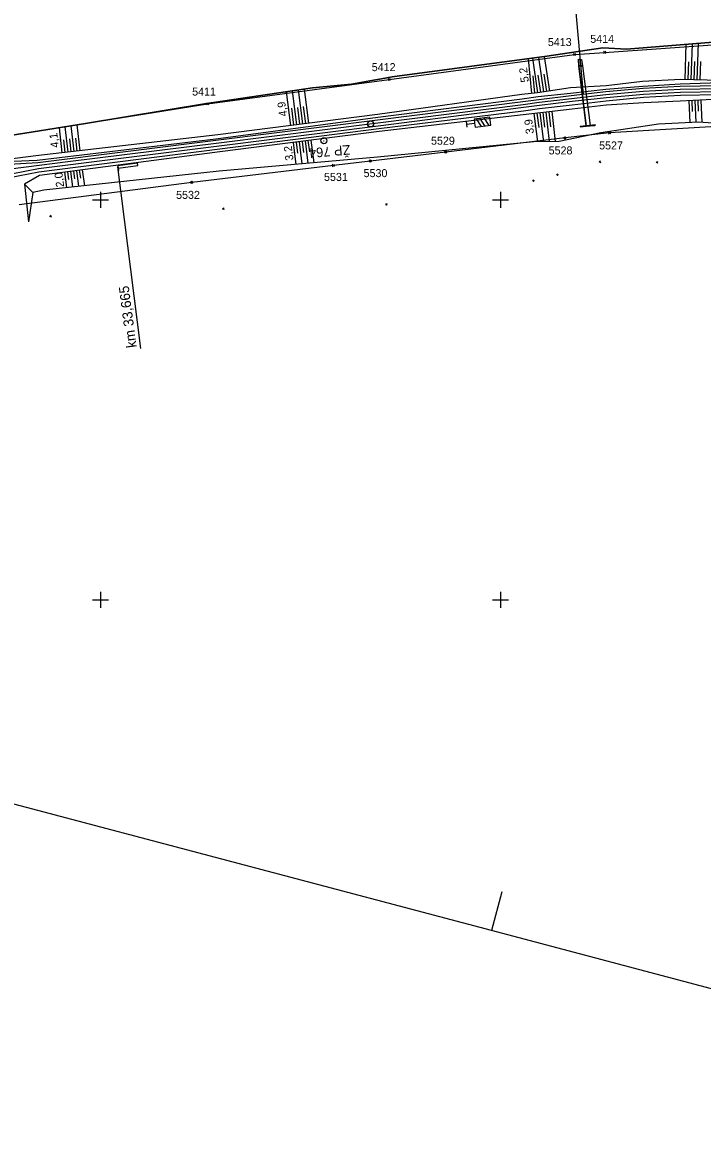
# Model space of a CAD drawing. Extents: x -805011 to -803920, y -1150790 to -1150234.
# Drawn here: x -804519.5 to -804349.5, y -1150736.4 to -1150455.7 of the extents above; entities that cross this region are included whole.
import ezdxf

# ---------------------------------------------------------------- set-up
doc = ezdxf.new("R2010")
doc.units = 0
for name, color, linetype in [('0381KM032-037P - Vrstva 1', 7, 'Continuous'), ('0381KM032-037P - Vrstva 17', 7, 'Continuous'), ('0381KM032-037P - Vrstva 19', 7, 'Continuous'), ('0381KM032-037P - Vrstva 4', 7, 'Continuous'), ('0381KM032-037P - Vrstva 48', 7, 'Continuous'), ('0381KM032-037P - Vrstva 49', 7, 'Continuous'), ('0381KM032-037P - Vrstva 7', 7, 'Continuous'), ('0381KM032-037P - Vrstva 9', 7, 'Continuous'), ('formát', 7, 'Continuous'), ('krizky_1000 - Vrstva 1', 7, 'Continuous'), ('szdc - hran DP', 7, 'Continuous'), ('szdc - szdc_cislo', 7, 'Continuous'), ('szdc - szdc_krizek', 7, 'Continuous'), ('vyt_sit - stávající', 7, 'Continuous')]:
    doc.layers.add(name, color=color, linetype=linetype)

msp = doc.modelspace()

# ---------------------------------------------------------------- linework, layer by layer
at = {"layer": '0381KM032-037P - Vrstva 1'}
for points in [[(-804345.19, -1150472.22), (-804355.1, -1150472.39), (-804364.37, -1150472.93), (-804373.68, -1150473.77), (-804382.25, -1150474.73), (-804390.38, -1150475.71), (-804394.38, -1150476.22)], [(-804394.38, -1150476.22), (-804430.66, -1150480.81), (-804470.38, -1150485.81), (-804485.9, -1150487.74)], [(-804485.9, -1150487.74), (-804508.11, -1150490.55), (-804529.67, -1150493.3), (-804537.63, -1150494.31), (-804546.61, -1150495.46), (-804554.2, -1150496.42), (-804564.05, -1150497.67), (-804586.01, -1150500.48), (-804607.92, -1150503.26), (-804630.35, -1150506.11), (-804652.65, -1150508.9), (-804675.7, -1150511.78), (-804698.85, -1150514.71), (-804701.61, -1150515.06), (-804722.18, -1150517.67), (-804729.05, -1150518.54), (-804735.1, -1150519.31), (-804744.56, -1150520.5), (-804767.65, -1150523.46), (-804791, -1150526.42)]]:
    msp.add_lwpolyline(points, dxfattribs=at)
at = {"layer": '0381KM032-037P - Vrstva 17'}
for points in [[(-804328.85, -1150461.67), (-804338.71, -1150460.38), (-804346.87, -1150460.56), (-804368.54, -1150462.33)], [(-804368.54, -1150462.33), (-804374.42, -1150462.03), (-804388.45, -1150464.13), (-804427.08, -1150469.25), (-804429.72, -1150469.73), (-804431.75, -1150470.1), (-804437.24, -1150471.08), (-804446.96, -1150472.02), (-804473.97, -1150476), (-804503.76, -1150480.94), (-804524.61, -1150484.28), (-804530.6, -1150485.02), (-804536.33, -1150485.99), (-804541.81, -1150485.21), (-804546.58, -1150482.25), (-804551.41, -1150478.74), (-804558.4, -1150472.14)]]:
    msp.add_lwpolyline(points, dxfattribs=at)
at = {"layer": '0381KM032-037P - Vrstva 19'}
for p, q in [((-804384.94, -1150412.13), (-804379.37, -1150473.64)), ((-804380.55, -1150464.84), (-804380.55, -1150464.84)), ((-804378.59, -1150481.54), (-804380.47, -1150466.54)), ((-804380.44, -1150466.61), (-804378.59, -1150481.59)), ((-804379.54, -1150466.49), (-804379.54, -1150466.49)), ((-804379.54, -1150466.49), (-804377.61, -1150481.41)), ((-804378.59, -1150481.59), (-804377.64, -1150481.48))]:
    msp.add_line(p, q, dxfattribs=at)
for points in [[(-804380.55, -1150464.84), (-804380.57, -1150464.89), (-804380.47, -1150466.54)], [(-804380.44, -1150466.61), (-804380.55, -1150464.84), (-804379.8, -1150464.93), (-804379.51, -1150466.55)], [(-804379.51, -1150466.55), (-804379.54, -1150466.49), (-804380.47, -1150466.54), (-804380.44, -1150466.61), (-804379.51, -1150466.55)], [(-804379.54, -1150466.49), (-804380.47, -1150466.54), (-804380.47, -1150466.54)], [(-804379.8, -1150464.93), (-804379.76, -1150464.9), (-804379.54, -1150466.49)]]:
    msp.add_lwpolyline(points, dxfattribs=at)
for points in [[(-804380.55, -1150464.84), (-804380.55, -1150464.84)], [(-804378.59, -1150481.54), (-804377.61, -1150481.41), (-804377.64, -1150481.48), (-804376.42, -1150481.39), (-804376.29, -1150481.28), (-804380.1, -1150481.67), (-804380.08, -1150481.76), (-804378.59, -1150481.59)]]:
    msp.add_lwpolyline(points, close=True, dxfattribs=at)
at = {"layer": '0381KM032-037P - Vrstva 4'}
for p, q in [((-804515.79, -1150490.21), (-804529.7, -1150490.74)), ((-804515.61, -1150490.8), (-804529.7, -1150491.57)), ((-804515.43, -1150492.3), (-804529.48, -1150494.97)), ((-804515.43, -1150492.3), (-804515.43, -1150492.3)), ((-804515.37, -1150493.06), (-804529.38, -1150495.79)), ((-804515.37, -1150493.06), (-804515.37, -1150493.06))]:
    msp.add_line(p, q, dxfattribs=at)
for points in [[(-804225.7, -1150511.47), (-804233.93, -1150505.38), (-804241.84, -1150500.35), (-804251.18, -1150495.03), (-804260.27, -1150490.25), (-804271.39, -1150485.02), (-804282.1, -1150481.42), (-804291.28, -1150478.15), (-804302, -1150475.62), (-804311.22, -1150473.82), (-804320.47, -1150472.35), (-804331.17, -1150471.28), (-804341.36, -1150470.84), (-804345.11, -1150470.79), (-804355.15, -1150471.09), (-804364.49, -1150471.64), (-804373.72, -1150472.46), (-804382.56, -1150473.46), (-804390.64, -1150474.3), (-804394.58, -1150474.82), (-804430.68, -1150479.4), (-804471.16, -1150484.87), (-804515.79, -1150490.21)], [(-804222.47, -1150514.31), (-804225.93, -1150511.88), (-804233.81, -1150506.22), (-804242.12, -1150500.85), (-804250.57, -1150495.96), (-804260.44, -1150490.89), (-804271.28, -1150486.07), (-804282.21, -1150481.99), (-804291.28, -1150479.14), (-804302.11, -1150476.36), (-804311.33, -1150474.54), (-804320.55, -1150473.14), (-804330.83, -1150472.06), (-804341.5, -1150471.52), (-804345.16, -1150471.47), (-804355.1, -1150471.64), (-804364.39, -1150472.17), (-804373.73, -1150473.02), (-804382.33, -1150473.97), (-804390.45, -1150474.97), (-804394.45, -1150475.48), (-804430.79, -1150480.07), (-804470.48, -1150485.06), (-804515.61, -1150490.8)], [(-804223.37, -1150515.97), (-804226.85, -1150513.1), (-804234.67, -1150507.48), (-804242.93, -1150502.16), (-804251.31, -1150497.29), (-804261.13, -1150492.25), (-804271.85, -1150487.49), (-804282.71, -1150483.42), (-804291.73, -1150480.59), (-804302.46, -1150477.85), (-804311.66, -1150476.01), (-804320.71, -1150474.65), (-804330.94, -1150473.58), (-804341.55, -1150473.05), (-804345.16, -1150472.99), (-804355.02, -1150473.16), (-804364.28, -1150473.69), (-804373.57, -1150474.51), (-804382.12, -1150475.46), (-804390.26, -1150476.46), (-804394.25, -1150476.96), (-804430.61, -1150481.56), (-804470.33, -1150486.56), (-804515.43, -1150492.3)], [(-804235.83, -1150507.71), (-804243.11, -1150502.63), (-804252.43, -1150497.68), (-804261.4, -1150493.06), (-804272.11, -1150488.47), (-804283.06, -1150484.22), (-804291.82, -1150481.32), (-804302.89, -1150478.85), (-804311.92, -1150476.81), (-804320.92, -1150475.47), (-804331.06, -1150474.34), (-804341.56, -1150473.81), (-804345.45, -1150473.75), (-804355.04, -1150473.96), (-804364.32, -1150474.45), (-804373.64, -1150475.34), (-804382.1, -1150476.35), (-804390.24, -1150477.29), (-804394.24, -1150477.85), (-804430.45, -1150482.3), (-804470.19, -1150487.36), (-804515.37, -1150493.06)]]:
    msp.add_lwpolyline(points, dxfattribs=at)
at = {"layer": '0381KM032-037P - Vrstva 48'}
for p, q in [((-804353.86, -1150469.92), (-804353.59, -1150461.11)), ((-804352.36, -1150469.97), (-804352.08, -1150460.99)), ((-804350.86, -1150470.01), (-804350.58, -1150460.86)), ((-804387.73, -1150472.81), (-804389, -1150464.2)), ((-804392.19, -1150473.4), (-804393.06, -1150464.74)), ((-804390.7, -1150473.25), (-804391.97, -1150464.6)), ((-804389.22, -1150473.03), (-804390.48, -1150464.4)), ((-804353.11, -1150469.95), (-804352.97, -1150465.5)), ((-804351.61, -1150469.99), (-804351.47, -1150465.46)), ((-804350.11, -1150470.04), (-804349.97, -1150465.42)), ((-804391.45, -1150473.33), (-804391.88, -1150468.99)), ((-804389.96, -1150473.14), (-804390.59, -1150468.82)), ((-804388.47, -1150472.92), (-804389.11, -1150468.61)), ((-804450.91, -1150481.22), (-804451.98, -1150472.76)), ((-804449.42, -1150481.03), (-804450.5, -1150472.54)), ((-804447.93, -1150480.84), (-804449.02, -1150472.32)), ((-804452.39, -1150481.41), (-804453.47, -1150472.98)), ((-804352.98, -1150475.24), (-804352.72, -1150480.7)), ((-804352.23, -1150475.2), (-804352.1, -1150477.93)), ((-804351.48, -1150475.16), (-804351.22, -1150480.62)), ((-804350.73, -1150475.13), (-804350.6, -1150477.86)), ((-804349.98, -1150475.09), (-804349.71, -1150480.65)), ((-804451.65, -1150481.31), (-804452.19, -1150477.09)), ((-804450.16, -1150481.12), (-804450.7, -1150476.89)), ((-804448.67, -1150480.93), (-804449.22, -1150476.68)), ((-804390.93, -1150478.35), (-804390.48, -1150481.91)), ((-804390.19, -1150478.25), (-804389.27, -1150485.47)), ((-804389.44, -1150478.17), (-804389.05, -1150481.81)), ((-804388.69, -1150478.09), (-804387.9, -1150485.45)), ((-804387.95, -1150478.01), (-804387.55, -1150481.72)), ((-804387.2, -1150477.93), (-804386.39, -1150485.42)), ((-804391.67, -1150478.44), (-804390.78, -1150485.49)), ((-804509.52, -1150488.25), (-804510.24, -1150481.98)), ((-804508.03, -1150488.07), (-804508.76, -1150481.74)), ((-804506.54, -1150487.9), (-804507.28, -1150481.5)), ((-804505.05, -1150487.73), (-804505.79, -1150481.27)), ((-804508.77, -1150488.16), (-804509.14, -1150485.01)), ((-804507.28, -1150487.99), (-804507.65, -1150484.8)), ((-804505.79, -1150487.81), (-804506.16, -1150484.6)), ((-804451.85, -1150485.69), (-804451.15, -1150491.14)), ((-804451.1, -1150485.59), (-804450.75, -1150488.33)), ((-804450.36, -1150485.49), (-804449.65, -1150491.01)), ((-804449.62, -1150485.4), (-804449.26, -1150488.17)), ((-804448.87, -1150485.3), (-804448.15, -1150490.87)), ((-804448.13, -1150485.21), (-804447.77, -1150488.01)), ((-804447.39, -1150485.11), (-804446.66, -1150490.74)), ((-804508.98, -1150493.12), (-804508.48, -1150496.95)), ((-804508.23, -1150493.02), (-804507.98, -1150494.94)), ((-804507.49, -1150492.92), (-804506.99, -1150496.79)), ((-804506.75, -1150492.83), (-804506.49, -1150494.77)), ((-804506, -1150492.73), (-804505.49, -1150496.63)), ((-804505.26, -1150492.63), (-804505.01, -1150494.59)), ((-804504.52, -1150492.53), (-804504, -1150496.47))]:
    msp.add_line(p, q, dxfattribs=at)
at = {"layer": '0381KM032-037P - Vrstva 49'}
for p, q in [((-804375.44, -1150490.42), (-804374.98, -1150490.64)), ((-804375.1, -1150490.3), (-804375.32, -1150490.76)), ((-804361.14, -1150490.51), (-804360.68, -1150490.73)), ((-804360.8, -1150490.39), (-804361.02, -1150490.85)), ((-804392.06, -1150495.11), (-804391.6, -1150495.33)), ((-804391.72, -1150494.99), (-804391.94, -1150495.45)), ((-804386.04, -1150493.59), (-804385.58, -1150493.81)), ((-804385.7, -1150493.47), (-804385.92, -1150493.93)), ((-804518.94, -1150496.06), (-804516.85, -1150498.14)), ((-804469.54, -1150502.14), (-804469.08, -1150502.36)), ((-804469.2, -1150502.02), (-804469.42, -1150502.48)), ((-804428.79, -1150501.05), (-804428.33, -1150501.27)), ((-804428.45, -1150500.93), (-804428.67, -1150501.39)), ((-804512.71, -1150504), (-804512.25, -1150504.22)), ((-804512.37, -1150503.88), (-804512.59, -1150504.34))]:
    msp.add_line(p, q, dxfattribs=at)
for points in [[(-804541.81, -1150485.21), (-804536.33, -1150485.99), (-804530.6, -1150485.02), (-804524.61, -1150484.28), (-804503.76, -1150480.94), (-804473.97, -1150476), (-804446.96, -1150472.02), (-804437.24, -1150471.08), (-804431.75, -1150470.1), (-804429.72, -1150469.73), (-804427.08, -1150469.25), (-804388.45, -1150464.13), (-804374.42, -1150462.03), (-804368.54, -1150462.33), (-804346.87, -1150460.56), (-804338.71, -1150460.38), (-804328.85, -1150461.67), (-804323.06, -1150462.29), (-804320.34, -1150463.27)], [(-804345.1, -1150470.19), (-804354.95, -1150469.89), (-804364.53, -1150470.46), (-804373.6, -1150471.54), (-804382.52, -1150472.05), (-804390.77, -1150473.26), (-804394.69, -1150473.65), (-804430.78, -1150478.65), (-804470.67, -1150483.74), (-804516.1, -1150489.01), (-804529.7, -1150490.74)], [(-804226.97, -1150514.32), (-804233.94, -1150510.78), (-804236.52, -1150508.57), (-804243.93, -1150503.82), (-804252.72, -1150498.82), (-804262.25, -1150494.6), (-804273.33, -1150489.4), (-804283.59, -1150485.01), (-804292.89, -1150482.47), (-804303.02, -1150479.68), (-804312.2, -1150478.16), (-804321.12, -1150476.62), (-804331.14, -1150475.24), (-804341.8, -1150475.06), (-804345.41, -1150474.87), (-804355.14, -1150475.34), (-804364.22, -1150475.73), (-804373.58, -1150476.33), (-804382.14, -1150477.38), (-804390.01, -1150478.23), (-804394.36, -1150478.78), (-804430.35, -1150482.91), (-804470.16, -1150488.05), (-804515.21, -1150493.93)], [(-804276.15, -1150497.56), (-804284.03, -1150490.16), (-804299.15, -1150485.83), (-804306.89, -1150483.98), (-804317.28, -1150482.7), (-804327.05, -1150481.84), (-804338.6, -1150481.41), (-804350.55, -1150480.59), (-804360.54, -1150481.11), (-804374.96, -1150483.29), (-804385.39, -1150485.41), (-804391.71, -1150485.5), (-804430.73, -1150489.32), (-804470.3, -1150492.85), (-804514.17, -1150497.56)], [(-804515.21, -1150493.93), (-804518.94, -1150496.06), (-804517.94, -1150505.51)], [(-804514.17, -1150497.56), (-804516.85, -1150498.14), (-804517.94, -1150505.51)]]:
    msp.add_lwpolyline(points, dxfattribs=at)
at = {"layer": '0381KM032-037P - Vrstva 7'}
for p, q in [((-804408.58, -1150480.36), (-804408.4, -1150481.84)), ((-804406.13, -1150479.8), (-804404.89, -1150481.66)), ((-804403.9, -1150481.54), (-804405.14, -1150479.68)), ((-804404.15, -1150479.55), (-804402.91, -1150481.41))]:
    msp.add_line(p, q, dxfattribs=at)
msp.add_lwpolyline([(-804408.49, -1150481.1), (-804406.51, -1150480.85), (-804406.38, -1150481.85), (-804402.41, -1150481.35), (-804402.66, -1150479.37), (-804406.63, -1150479.86), (-804406.51, -1150480.85)], dxfattribs=at)
msp.add_circle((-804432.47, -1150481.04), 0.75, dxfattribs=at)
at = {"layer": '0381KM032-037P - Vrstva 9'}
for p, q in [((-804490.7, -1150490.86), (-804495.66, -1150491.5)), ((-804495.66, -1150491.5), (-804495.58, -1150492.1)), ((-804489.86, -1150537.15), (-804495.62, -1150491.8)), ((-804495.58, -1150492.1), (-804490.62, -1150491.45)), ((-804495.58, -1150492.1), (-804495.5, -1150492.69)), ((-804490.62, -1150491.45), (-804490.7, -1150490.86))]:
    msp.add_line(p, q, dxfattribs=at)
at = {"layer": 'formát'}
for p, q in [((-804402.28, -1150682.7), (-805011.32, -1150521.54)), ((-804399.72, -1150673.03), (-804402.28, -1150682.7)), ((-804399.72, -1150673.03), (-804402.28, -1150682.7)), ((-804199.27, -1150736.42), (-804402.28, -1150682.7))]:
    msp.add_line(p, q, dxfattribs=at)
at = {"layer": 'krizky_1000 - Vrstva 1'}
for points in [[(-804500, -1150498), (-804500, -1150502)], [(-804400, -1150498), (-804400, -1150502)], [(-804502, -1150500), (-804498, -1150500)], [(-804402, -1150500), (-804398, -1150500)], [(-804500, -1150598), (-804500, -1150602)], [(-804400, -1150598), (-804400, -1150602)], [(-804502, -1150600), (-804498, -1150600)], [(-804402, -1150600), (-804398, -1150600)]]:
    msp.add_lwpolyline(points, dxfattribs=at)
at = {"layer": 'szdc - hran DP'}
for p, q in [((-804374.01, -1150463.14), (-804345.91, -1150461.18)), ((-804427.86, -1150469.92), (-804381.52, -1150463.67)), ((-804381.52, -1150463.67), (-804374.01, -1150463.14)), ((-804473.24, -1150476.04), (-804427.86, -1150469.92)), ((-804532.83, -1150485.53), (-804473.24, -1150476.04)), ((-804372.75, -1150483.24), (-804383.87, -1150484.55)), ((-804340.86, -1150481.33), (-804372.75, -1150483.24)), ((-804383.87, -1150484.55), (-804413.66, -1150488.07)), ((-804413.66, -1150488.07), (-804432.51, -1150490.32)), ((-804441.78, -1150491.42), (-804477.16, -1150495.64)), ((-804432.51, -1150490.32), (-804441.78, -1150491.42)), ((-804477.16, -1150495.64), (-804520.26, -1150501.29))]:
    msp.add_line(p, q, dxfattribs=at)
at = {"layer": 'szdc - szdc_krizek'}
for p, q in [((-804381.26, -1150463.94), (-804381.79, -1150463.41)), ((-804381.79, -1150463.94), (-804381.26, -1150463.41)), ((-804373.74, -1150463.41), (-804374.28, -1150462.88)), ((-804374.28, -1150463.41), (-804373.74, -1150462.88)), ((-804427.59, -1150470.19), (-804428.13, -1150469.66)), ((-804428.13, -1150470.19), (-804427.59, -1150469.66)), ((-804472.97, -1150476.3), (-804473.51, -1150475.78)), ((-804473.51, -1150476.3), (-804472.97, -1150475.78)), ((-804372.48, -1150483.51), (-804373.02, -1150482.98)), ((-804373.02, -1150483.51), (-804372.48, -1150482.98)), ((-804383.6, -1150484.81), (-804384.14, -1150484.28)), ((-804384.14, -1150484.81), (-804383.6, -1150484.28)), ((-804413.4, -1150488.33), (-804413.93, -1150487.8)), ((-804413.93, -1150488.33), (-804413.4, -1150487.8)), ((-804441.52, -1150491.69), (-804442.05, -1150491.16)), ((-804442.05, -1150491.69), (-804441.52, -1150491.16)), ((-804432.24, -1150490.58), (-804432.78, -1150490.05)), ((-804432.78, -1150490.58), (-804432.24, -1150490.05)), ((-804476.9, -1150495.91), (-804477.43, -1150495.38)), ((-804477.43, -1150495.91), (-804476.9, -1150495.38))]:
    msp.add_line(p, q, dxfattribs=at)
at = {"layer": 'vyt_sit - stávající'}
msp.add_line((-804444.21, -1150485.23), (-804444.1, -1150485.23), dxfattribs=at)
msp.add_circle((-804444.16, -1150485.23), 0.756, dxfattribs=at)

# ---------------------------------------------------------------- texts
at = {"layer": '0381KM032-037P - Vrstva 48'}
for s, rotation, p in [('5,2', 97.5493, (-804392.93, -1150470.51)), ('4,9', 98.3966, (-804453.3, -1150479.03)), ('3,9', 97.2061, (-804391.65, -1150483.43)), ('4,1', 96.6169, (-804510.37, -1150486.87)), ('3,2', 97.3569, (-804451.73, -1150490.07)), ('2,0', 97.4363, (-804509.04, -1150496.72))]:
    msp.add_text(s, height=2, rotation=rotation, dxfattribs=at).set_placement(p)
at = {"layer": '0381KM032-037P - Vrstva 9'}
msp.add_text('km 33,665', height=2.5, rotation=97.4056, dxfattribs=at).set_placement((-804490.93, -1150536.84))
at = {"layer": 'szdc - szdc_cislo'}
for s, p in [('5413', (-804388.19, -1150461.57)), ('5414', (-804377.59, -1150460.77)), ('5412', (-804432.19, -1150467.84)), ('5411', (-804477.07, -1150473.95)), ('5529', (-804417.38, -1150486.23)), ('5528', (-804387.99, -1150488.66)), ('5527', (-804375.38, -1150487.41)), ('5530', (-804434.23, -1150494.33)), ('5531', (-804444.12, -1150495.28)), ('5532', (-804481.08, -1150499.77))]:
    msp.add_text(s, height=2, dxfattribs=at).set_placement(p)
at = {"layer": 'vyt_sit - stávající'}
msp.add_text('ŽP 764', height=2.4, rotation=185, dxfattribs=at).set_placement((-804437.66, -1150486.27))

doc.saveas('drawing.dxf')
